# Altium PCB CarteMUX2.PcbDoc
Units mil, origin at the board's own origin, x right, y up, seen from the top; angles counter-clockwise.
Board outline 6000 x 4000 mil, 2 copper layers (Top Layer, Bottom Layer); 13 components, 51 nets, 144 pads, 0 vias.
Unrouted connection lines stored in the file: 54.
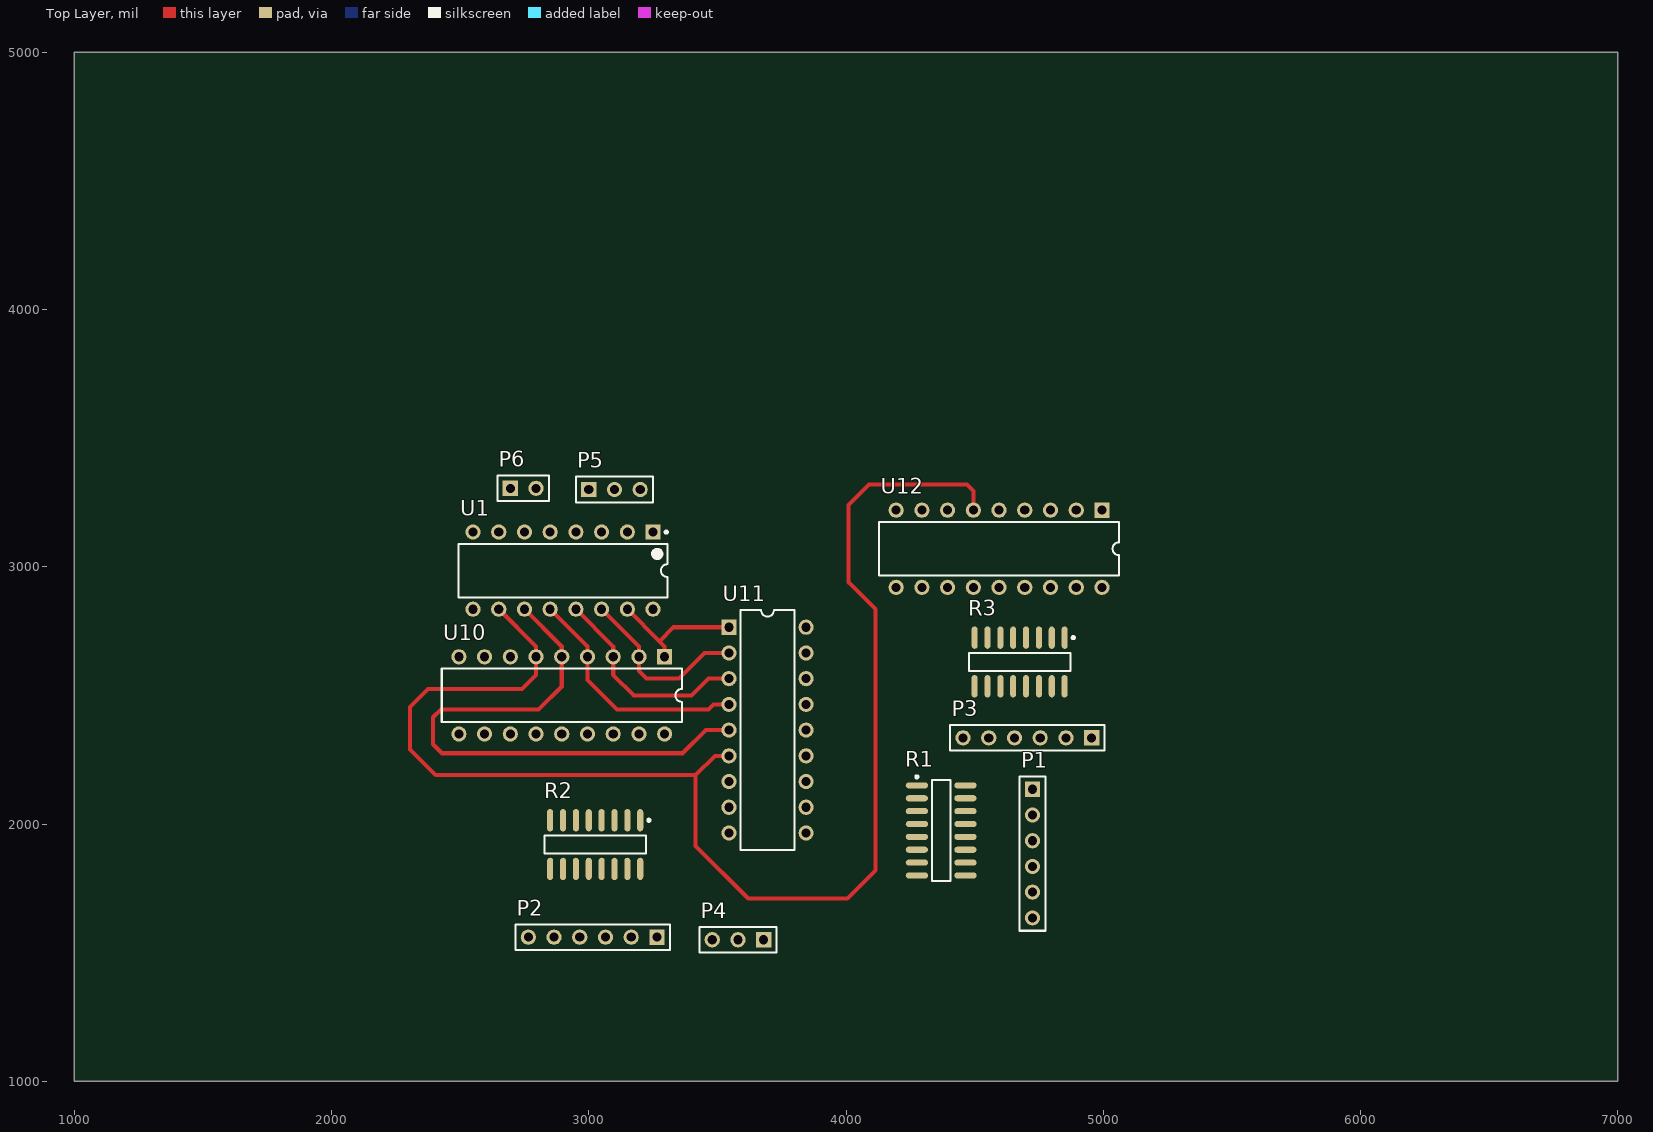
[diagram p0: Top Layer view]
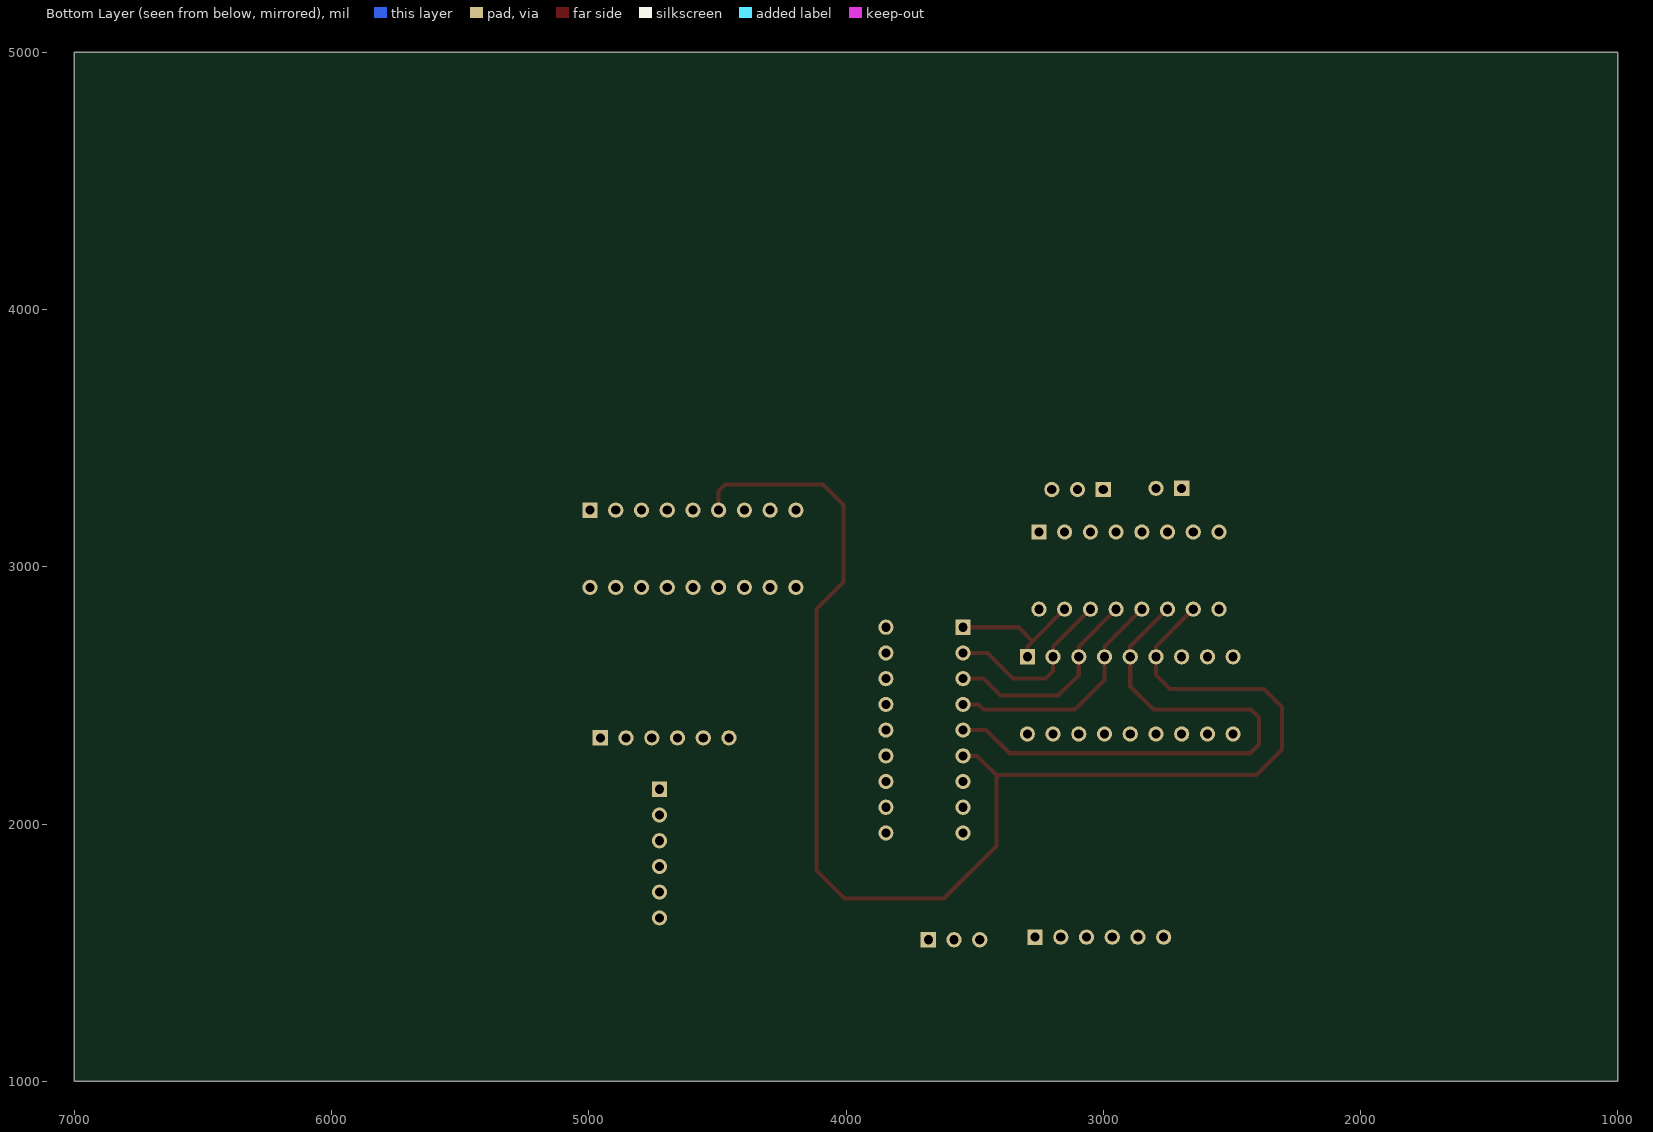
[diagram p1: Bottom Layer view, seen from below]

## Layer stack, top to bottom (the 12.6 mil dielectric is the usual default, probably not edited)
Top Layer: signal copper 1.4
Dielectric: dielectric 12.6, FR-4, Dk 4.8
Bottom Layer: signal copper 1.4

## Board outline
1000,1000 7000,1000 7000,5000 1000,5000

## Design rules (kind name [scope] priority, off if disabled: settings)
Clearance [All] p1: gap=15.75
PolygonConnect [All] p1: connectstyle=Relief reliefconductorwidth=10 reliefentries=4 polygonreliefangle="90 Angle" airgapwidth=10
RoomDefinition CarteMUX2 [InComponentClass('CarteMUX2')] p1: confinementstyle=ConfineIn formatcopy=TRUE lockcomponents=FALSE outline 1790,-40 5480,-40 5480,1020 1790,1020
RoutingVias [All] p1: holewidth=28 width=50 viastyle="Through Hole" minholewidth=28 minwidth=50 maxholewidth=28 maxwidth=50
SilkscreenOverComponentPads [All] p1: minsilkscreentomaskgap=10
SolderMaskExpansion [All] p1: expansion=4
Width [All] p1: maxlimit=16 minlimit=10 preferedwidth=16
27 further rules are at their usual default settings.

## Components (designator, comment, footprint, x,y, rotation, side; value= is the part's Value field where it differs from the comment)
P1 "Header 6" HDR1X6 4725,2135 r270 top
P2 "Header 6" HDR1X6 3265,1560 r180 top
P3 "Header 6" HDR1X6 4955,2335 r180 top
P4 "Header 3" HDR1X3 3680,1550 r180 top
P5 "Header 3" HDR1X3 3000,3300 r0 top
P6 "Header 2" HDR1X2 2695,3305 r0 top
R1 "Res Pack3" SO-16_N 4370,1975 r0 top
R2 "Res Pack3" SO-16_N 3025,1920 r270 top
R3 "Res Pack3" SO-16_N 4675,2630 r270 top
U1 "74AC138PC" N16E 2900,2985 r270 top
U10 "ULQ2803A" DIP18 2895,2500 r180 top
U11 "ULQ2803A" DIP18 3695,2365 r270 top
U12 "ULQ2803A" DIP18 4595,3070 r180 top

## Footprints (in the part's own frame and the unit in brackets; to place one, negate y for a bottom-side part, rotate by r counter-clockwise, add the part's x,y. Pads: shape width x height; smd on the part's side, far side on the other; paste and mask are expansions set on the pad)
DIP18 [mm] "DIP; 18 Leads; Row Spacing 7.62 mm; Pitch 2.54 mm"
  rect 1.5x1.5 hole 0.9: 1(-10.16,-3.81)
  round 1.5 hole 0.9: 2(-7.62,-3.81) 3(-5.08,-3.81) 4(-2.54,-3.81) 5(0,-3.81) 6(2.54,-3.81) 7(5.08,-3.81) 8(7.62,-3.81) 9(10.16,-3.81) 10(10.16,3.81) 11(7.62,3.81) 12(5.08,3.81) 13(2.54,3.81) 14(0,3.81) 15(-2.54,3.81) 16(-5.08,3.81) 17(-7.62,3.81) 18(-10.16,3.81)
  silkscreen extent -11.85,-2.65 11.85,2.65
HDR1X2 [mm] "Connector; Header; 2 Position"
  rect 1.5x1.5 hole 0.9: 1(0,0)
  round 1.5 hole 0.9: 2(2.54,0)
  silkscreen extent -1.27,-1.27 3.81,1.27
HDR1X3 [mm] "Connector; Header; 3 Position"
  rect 1.5x1.5 hole 0.9: 1(0,0)
  round 1.5 hole 0.9: 2(2.54,0) 3(5.08,0)
  silkscreen extent -1.27,-1.27 6.35,1.27
HDR1X6 [mm] "Connector; Header; 6 Position"
  rect 1.5x1.5 hole 0.9: 1(0,0)
  round 1.5 hole 0.9: 2(2.54,0) 3(5.08,0) 4(7.62,0) 5(10.16,0) 6(12.7,0)
  silkscreen extent -1.27,-1.27 13.97,1.27
N16E [mm] "DIP, 16-Leads, Row Spacing 7.62mm, Pitch 2.54mm, Body 19.3x6.35mm"
  rect 1.5x1.5 hole 0.9: 1(-3.81,8.89)
  round 1.5 hole 0.9: 2(-3.81,6.35) 3(-3.81,3.81) 4(-3.81,1.27) 5(-3.81,-1.27) 6(-3.81,-3.81) 7(-3.81,-6.35) 8(-3.81,-8.89) 9(3.81,-8.89) 10(3.81,-6.35) 11(3.81,-3.81) 12(3.81,-1.27) 13(3.81,1.27) 14(3.81,3.81) 15(3.81,6.35) 16(3.81,8.89)
  silkscreen extent -3.93,-10.3 2.65,10.32, body extent -3.6,-10.28 3.6,10.28, height 5.08
SO-16_N [mm] "SOIC, 16-Leads, Body 9.9x3.9mm, Pitch 1.27mm, IPC Medium Density"
  oval 2.2x0.6 smd: 1(-2.4,4.445) 2(-2.4,3.175) 3(-2.4,1.905) 4(-2.4,0.635) 5(-2.4,-0.635) 6(-2.4,-1.905) 7(-2.4,-3.175) 8(-2.4,-4.445) 9(2.4,-4.445) 10(2.4,-3.175) 11(2.4,-1.905) 12(2.4,-0.635) 13(2.4,0.635) 14(2.4,1.905) 15(2.4,3.175) 16(2.4,4.445)
  silkscreen extent -2.52,-5 0.9,5.42, body extent -2,-5 2,5, height 1.75

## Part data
P1 P2 P3: "Header, 6-Pin"
P4 P5: "Header, 3-Pin"
P6: "Header, 2-Pin"
R1 R2 R3: "Isolated Resistor Network"
U1: "1-of-8 Decoder/Multiplexer"
U10 U11 U12: "Eight Darlington Array"

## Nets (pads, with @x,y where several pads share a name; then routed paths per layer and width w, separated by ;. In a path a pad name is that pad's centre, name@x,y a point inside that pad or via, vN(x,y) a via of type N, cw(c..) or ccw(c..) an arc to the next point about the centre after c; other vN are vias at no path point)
GND: U10.9 U11.9 U12.9
NetP1_1: P1.1 R1.16
NetP1_2: P1.2 R1.15
NetP1_3: P1.3 R1.14
NetP1_4: P1.4 R1.13
NetP1_5: P1.5 R1.12
NetP1_6: P1.6 R1.11
NetP2_1: P2.1 R2.16
NetP2_2: P2.2 R2.15
NetP2_3: P2.3 R2.14
NetP2_4: P2.4 R2.13
NetP2_5: P2.5 R2.12
NetP2_6: P2.6 R2.11
NetP3_1: P3.1 R3.16
NetP3_2: P3.2 R3.15
NetP3_3: P3.3 R3.14
NetP3_4: P3.4 R3.13
NetP3_5: P3.5 R3.12
NetP3_6: P3.6 R3.11
NetP4_1: P4.1 U11.10
NetP4_2: P4.2 U10.10
NetP4_3: P4.3 U12.10
NetP5_1: P5.1 U1.3
NetP5_2: P5.2 U1.2
NetP5_3: P5.3 U1.1
NetP6_1: P6.1 U1.4 U1.5 U1.8
NetP6_2: P6.2 U1.6 U1.16
NetR1_1: R1.1 U11.18
NetR1_2: R1.2 U11.17
NetR1_3: R1.3 U11.16
NetR1_4: R1.4 U11.15
NetR1_5: R1.5 U11.14
NetR1_6: R1.6 U11.13
NetR2_1: R2.1 U10.18
NetR2_2: R2.2 U10.17
NetR2_3: R2.3 U10.16
NetR2_4: R2.4 U10.15
NetR2_5: R2.5 U10.14
NetR2_6: R2.6 U10.13
NetR3_1: R3.1 U12.18
NetR3_2: R3.2 U12.17
NetR3_3: R3.3 U12.16
NetR3_4: R3.4 U12.15
NetR3_5: R3.5 U12.14
NetR3_6: R3.6 U12.13
NetU1_10: U1.10 U10.6 U11.6 U12.6 | length 5506.8
  Top Layer w16: U1.10 2795,2690 U10.6 2795,2580 2740,2525 2375,2525 2305,2455 2305,2290 2405,2190 3415,2190 ; U11.6 3490,2265 3415,2190 ; U12.6 4495,3295 4470,3320 4090,3320 4010,3240 4010,2940 4115,2835 4115,1820 4005,1710 3620,1710 3415,1915 3415,2190
NetU1_11: U1.11 U10.5 U11.5 U12.5 | length 2216.5
  Top Layer w16: U1.11 2895,2690 U10.5 2895,2535 2805,2445 2425,2445 2395,2415 2395,2310 2430,2275 3365,2275 3455,2365 U11.5
NetU1_12: U1.12 U10.4 U11.4 U12.4 | length 941
  Top Layer w16: U1.12 2995,2690 U10.4 2995,2560 3110,2445 3465,2445 3485,2465 U11.4
NetU1_13: U1.13 U10.3 U11.3 U12.3 | length 825.1
  Top Layer w16: U1.13 3095,2690 U10.3 3095,2580 3175,2500 3400,2500 3465,2565 U11.3
NetU1_14: U1.14 U10.2 U11.2 U12.2 | length 703.9
  Top Layer w16: U1.14 3195,2690 U10.2 3195,2595 3225,2565 3350,2565 3450,2665 U11.2
NetU1_15: U1.15 U10.1 U11.1 U12.1 | length 537.8
  Top Layer w16: U1.15 3275,2710 ; U10.1 3295,2690 3275,2710 ; U11.1 3330,2765 3275,2710
pads on no net: R1.7 R1.8 R1.9 R1.10 R2.7 R2.8 R2.9 R2.10 R3.7 R3.8 R3.9 R3.10 U1.7 U1.9 U10.7 U10.8 U10.11 U10.12 U11.7 U11.8 U11.11 U11.12 U12.7 U12.8 U12.11 U12.12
